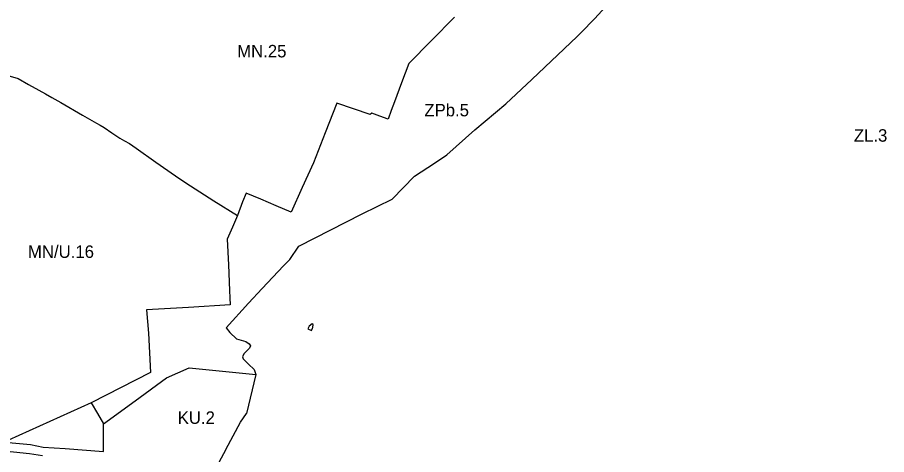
# Model space of a CAD drawing. Extents: x 7431080 to 7433370, y 5546450 to 5548428.
# Drawn here: x 7431991 to 7432547, y 5546820 to 5547100 of the extents above; entities that cross this region are included whole.
import ezdxf

# ---------------------------------------------------------------- set-up
doc = ezdxf.new("R2010")
doc.units = 0
for name, color, linetype in [('Linie Rozgraniczajace', 7, 'Continuous'), ('nieprzekraczalna linia zabudowy', 7, 'Continuous'), ('obowiązująca linia zabudowy', 7, 'Continuous'), ('oznaczenia_przeznaczen', 7, 'Continuous')]:
    doc.layers.add(name, color=color, linetype=linetype)

msp = doc.modelspace()

# ---------------------------------------------------------------- linework, layer by layer
at = {"layer": 'Linie Rozgraniczajace'}
msp.add_line((7432124.29, 5546823.16), (7432114.87, 5546805.62), dxfattribs=at)
for points in [[(7432371.12, 5547111.11), (7432370.13, 5547109.85), (7432369, 5547108.4), (7432368.36, 5547107.58), (7432367.41, 5547106.59), (7432359.99, 5547098.79), (7432351.61, 5547089.99), (7432349.01, 5547087.53)], [(7432270.53, 5547099.73), (7432255.89, 5547084.97), (7432241.25, 5547070.2), (7432236.7, 5547057.87), (7432232.15, 5547045.55), (7432230.11, 5547040.03), (7432228.07, 5547034.51), (7432222.86, 5547036.41), (7432217.59, 5547038.33), (7432216.7, 5547037.49), (7432206.03, 5547041.1), (7432195.35, 5547044.7), (7432187.83, 5547025.71), (7432180.31, 5547006.72), (7432173.2, 5546990.89), (7432166.1, 5546975.05), (7432156.4, 5546979.16), (7432146.7, 5546983.27), (7432141.95, 5546985.28), (7432137.21, 5546987.29), (7432135.04, 5546981.66), (7432131.78, 5546972.86), (7432128.51, 5546965.37), (7432125.23, 5546957.87), (7432125.99, 5546941.35), (7432126.75, 5546924.83), (7432126.95, 5546920.32), (7432127.16, 5546915.82), (7432100.34, 5546914.16), (7432073.52, 5546912.49), (7432074.83, 5546897.68), (7432075.43, 5546885.03), (7432076.03, 5546872.38), (7432038.13, 5546853.09), (7432011.7, 5546841.17), (7431985.27, 5546829.24)], [(7432161.19, 5546940.7), (7432165.14, 5546944.74), (7432170.93, 5546953.35), (7432211.5, 5546974.06), (7432221.12, 5546978.75), (7432230.73, 5546983.45), (7432245.04, 5546998), (7432257.67, 5547006.46), (7432265.63, 5547011.71), (7432283.54, 5547027.7), (7432303.47, 5547044.4), (7432319.98, 5547059.96), (7432349.01, 5547087.53)], [(7431977.34, 5547065.69), (7431983.49, 5547062.98), (7431991.41, 5547060.6), (7431998.07, 5547056.82), (7432004.72, 5547053.04), (7432008.92, 5547050.71), (7432013.11, 5547048.39), (7432018.79, 5547045.23), (7432032.74, 5547037.1), (7432041.51, 5547032.05)], [(7432041.51, 5547032.05), (7432044, 5547030.62), (7432046.5, 5547029.2), (7432051.48, 5547025.75), (7432056.46, 5547022.31), (7432059.55, 5547020.62), (7432062.64, 5547018.93), (7432064.79, 5547017.42), (7432066.94, 5547015.92), (7432079.54, 5547007.11), (7432092.14, 5546998.3), (7432098.03, 5546994.18), (7432101.63, 5546991.86), (7432116.71, 5546982.36), (7432131.78, 5546972.86)], [(7432161.19, 5546940.7), (7432147.63, 5546926.2), (7432138.85, 5546916.87), (7432124.6, 5546901.13), (7432126.85, 5546898.01), (7432131.18, 5546894.06), (7432137.18, 5546892.35), (7432139.26, 5546890.88), (7432140.06, 5546889.58), (7432139.44, 5546888.09), (7432137.58, 5546886.21), (7432135.73, 5546884.32), (7432135.02, 5546882.52), (7432135.31, 5546881.16), (7432138.84, 5546877.78), (7432142.37, 5546874.39), (7432143.52, 5546871.26)], [(7432038.13, 5546853.09), (7432042.13, 5546846.33), (7432046.14, 5546839.58), (7432066.29, 5546854.29), (7432086.45, 5546869.01), (7432093.66, 5546872.21), (7432100.86, 5546875.4), (7432143.52, 5546871.26)], [(7432143.52, 5546871.26), (7432137.47, 5546846.29)], [(7432124.29, 5546823.16), (7432133.71, 5546840.69), (7432137.47, 5546846.29)], [(7432007.05, 5546819.09), (7431998.82, 5546820.5), (7431971.93, 5546823.22), (7431969.09, 5546823.51)]]:
    msp.add_lwpolyline(points, dxfattribs=at)
at = {"layer": 'nieprzekraczalna linia zabudowy'}
msp.add_line((7432046.14, 5546821.94), (7432046.14, 5546839.58), dxfattribs=at)
msp.add_lwpolyline([(7431961.36, 5546830.01), (7431963.62, 5546829.81), (7431971.12, 5546829.14), (7431985.21, 5546827.73), (7431999.3, 5546826.31), (7432007.44, 5546824.79), (7432021.64, 5546823.84), (7432021.64, 5546823.84), (7432046.14, 5546821.94)], dxfattribs=at)
at = {"layer": 'obowiązująca linia zabudowy'}
msp.add_lwpolyline([(7432179.52, 5546900.25), (7432179.81, 5546900.8), (7432180.03, 5546901.23), (7432180.19, 5546903.14), (7432179.56, 5546903.51), (7432177.69, 5546902.19), (7432176.77, 5546900.43), (7432179.01, 5546899.26), (7432179.56, 5546900.31)], dxfattribs=at)

# ---------------------------------------------------------------- texts
at = {"layer": 'oznaczenia_przeznaczen'}
for s, p in [('MN.25', (7432131.55, 5547074.08)), ('ZPb.5', (7432251.27, 5547036.36)), ('ZPb.5', (7432251.27, 5547036.36)), ('ZL.3', (7432525.95, 5547020.14)), ('ZL.3', (7432525.95, 5547020.14)), ('MN/U.16', (7431997.76, 5546945.8)), ('KU.2', (7432093.52, 5546839.6)), ('KU.2', (7432093.52, 5546839.6)), ('KU.2', (7432093.52, 5546839.6))]:
    msp.add_text(s, height=8, dxfattribs=at).set_placement(p)

doc.saveas('drawing.dxf')
